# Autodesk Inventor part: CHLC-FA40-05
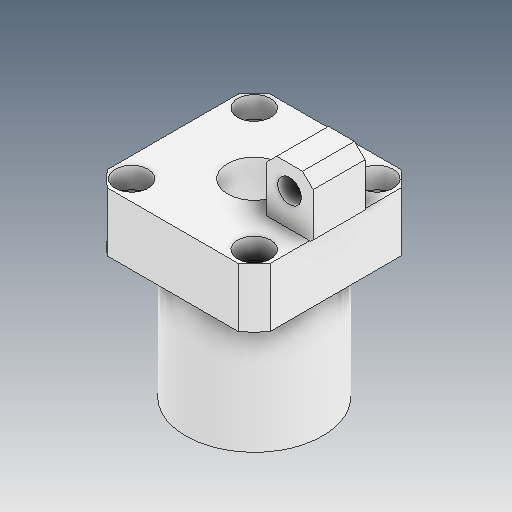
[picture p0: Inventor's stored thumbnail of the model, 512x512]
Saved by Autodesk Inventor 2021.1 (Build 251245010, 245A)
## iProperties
Created: 2021-05
Part Number: CHLC-FA40-05
Material: Ogólny
Document SubType Name: Modeling
Designer: user
Density: 1 g/cm^3
Appearance: Domyślna
Author: user
Revision Number: ÈÎºÎ
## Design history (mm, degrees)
feature "ÊäÈë1"
node "Bryła1"
